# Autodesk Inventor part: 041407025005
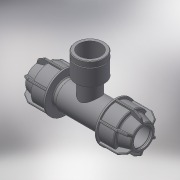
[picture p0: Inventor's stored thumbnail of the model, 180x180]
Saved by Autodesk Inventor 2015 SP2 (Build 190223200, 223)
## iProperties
Created: 2017-08
Part Number: 041407025005
Material: Generic
Description: PLASSON IRRIFIT TEE FEMALE ADAPTOR 25-1/2"-25
Document SubType Name: Modeling
Designer: KIM
Density: 1 g/cm^3
Appearance: Default
Author: KIM
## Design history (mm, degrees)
derived "041407.ipt"
feature "Solid1::041407.ipt"
feature "Solid2::041407.ipt"
tag "TaggingFeature1"
body "Solid1"
other parameters: "d1" = 25, "d2" = 31, "d4" = 15 deg, "d5" = 29.45, "d6" = 11.78, "d10" = 45, "d16" = 25.5, "d17" = 1.55, "d22" = 32.5, "d24" = 1.55, "d25" = 40.5, "d26" = 33.75, "d27" = 1.55, "d28" = 135 deg, "d29" = 0.93, "d31" = 1.25, "d46" = 150 deg, "d49" = 2.25, "d50" = 0, "d58" = 0.75, "d61" = 360 deg, "d63" = 22.5, "d64" = 53.5, "d80" = 35.75, "d81" = 0.25, "d94" = 48, "d96" = 24.2203, "d108" = 0.75, "d113" = 13.0417, "d115" = 19.2, "d117" = 16.7679, "d118" = 3.1, "d119" = 16, "d120" = 18.631, "d121" = 0.37262, "d122" = 4.8, "d123" = 3.1, "d128" = 24.2203, "d130" = 0, "d132" = 0, "d_" = 25, "G_" = 18.631, "E_" = 45, "H_" = 107, "l_" = 31, "l_1" = 16, "A_" = 48
